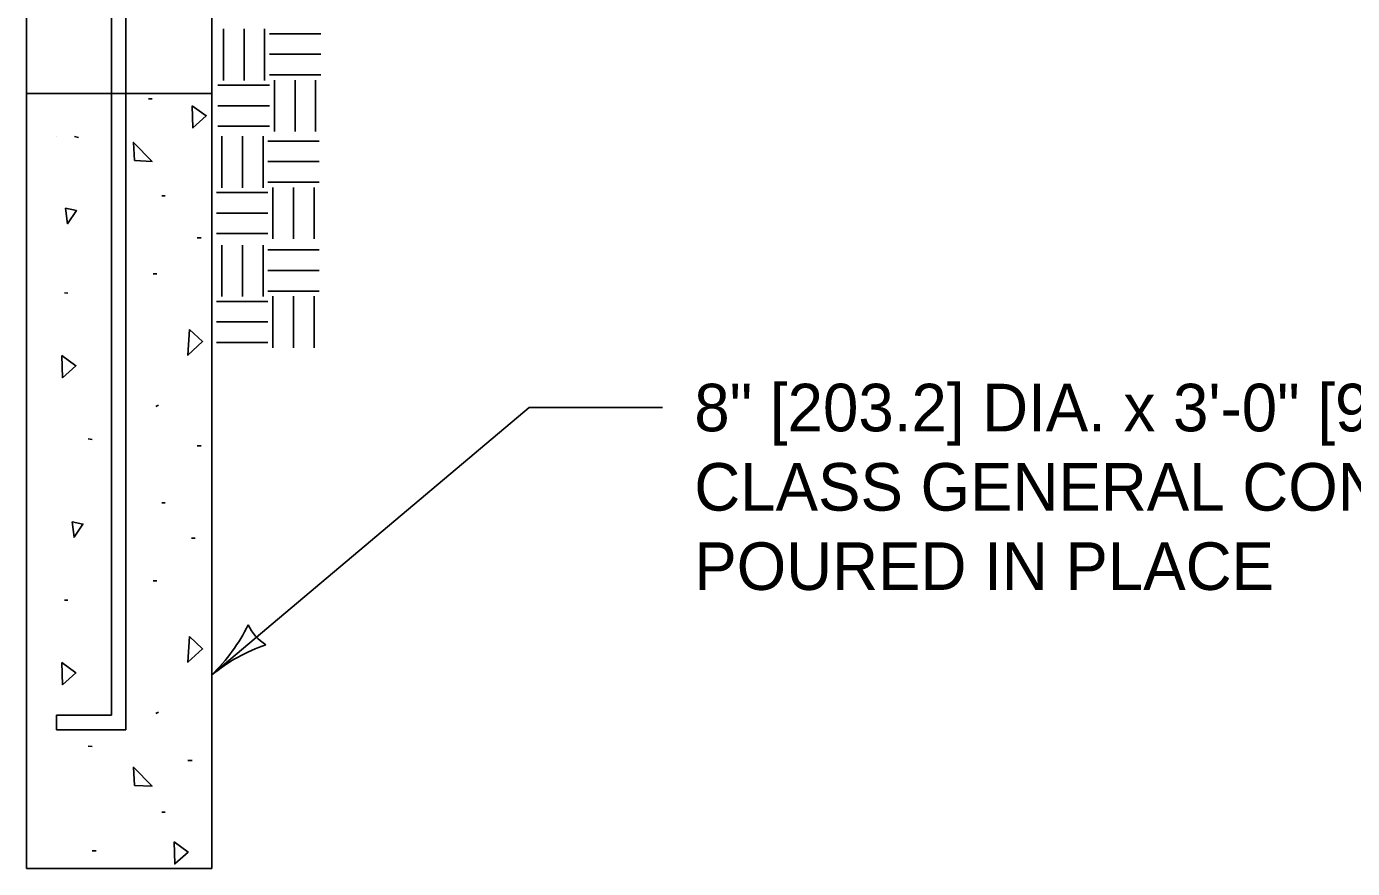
# Model space of a CAD drawing. Extents: x 49991.4 to 50021, y 49987.6 to 50011.4.
# Drawn here: x 50009.738 to 50011.41, y 49995.265 to 49996.327 of the extents above; entities that cross this region are included whole.
import ezdxf

# ---------------------------------------------------------------- set-up
doc = ezdxf.new("R2010")
doc.units = 0
for name, color, linetype in [('Level 1', 7, 'Continuous'), ('Level 2', 7, 'Continuous'), ('Level 3', 7, 'Continuous'), ('Level 4', 7, 'Continuous')]:
    doc.layers.add(name, color=color, linetype=linetype)

msp = doc.modelspace()

# ---------------------------------------------------------------- linework, layer by layer
at = {"layer": 'Level 1'}
for p, q in [((50009.8451, 49996.5973), (50009.8451, 49995.4586)), ((50009.8633, 49996.5973), (50009.8633, 49995.4401)), ((50009.9865, 49996.3237), (50009.9865, 49996.2589)), ((50010.0124, 49996.3237), (50010.0124, 49996.2589)), ((50010.0383, 49996.3237), (50010.0383, 49996.2589)), ((50010.0444, 49996.3177), (50010.1092, 49996.3177)), ((50010.0444, 49996.2918), (50010.1092, 49996.2918)), ((50010.0444, 49996.2658), (50010.1092, 49996.2658)), ((50009.9795, 49996.2528), (50010.0444, 49996.2528)), ((50010.0508, 49996.2593), (50010.0508, 49996.1945)), ((50010.0768, 49996.2593), (50010.0768, 49996.1945)), ((50010.1027, 49996.2593), (50010.1027, 49996.1945)), ((50009.7381, 49996.2425), (50009.9719, 49996.2425)), ((50009.7381, 49996.2425), (50009.7381, 49995.2651)), ((50009.892, 49996.2357), (50009.8964, 49996.2357)), ((50009.9719, 49995.2651), (50009.9719, 49996.2425)), ((50009.9795, 49996.2269), (50010.0444, 49996.2269)), ((50009.9795, 49996.2009), (50010.0444, 49996.2009)), ((50009.7764, 49996.1882), (50009.7764, 49996.1882)), ((50009.7987, 49996.1882), (50009.8037, 49996.187)), ((50009.9845, 49996.1883), (50009.9845, 49996.1235)), ((50010.0104, 49996.1883), (50010.0104, 49996.1235)), ((50010.0364, 49996.1883), (50010.0364, 49996.1235)), ((50010.0424, 49996.1823), (50010.1073, 49996.1823)), ((50010.0424, 49996.1564), (50010.1073, 49996.1564)), ((50009.9775, 49996.1175), (50010.0424, 49996.1175)), ((50010.0424, 49996.1304), (50010.1073, 49996.1304)), ((50010.0488, 49996.1239), (50010.0488, 49996.0591)), ((50010.0748, 49996.1239), (50010.0748, 49996.0591)), ((50010.1007, 49996.1239), (50010.1007, 49996.0591)), ((50009.9087, 49996.1134), (50009.913, 49996.1134)), ((50009.9775, 49996.0915), (50010.0424, 49996.0915)), ((50009.9775, 49996.0656), (50010.0424, 49996.0656)), ((50009.9533, 49996.0603), (50009.9582, 49996.0603)), ((50009.9845, 49996.051), (50009.9845, 49995.9862)), ((50010.0104, 49996.051), (50010.0104, 49995.9862)), ((50010.0364, 49996.051), (50010.0364, 49995.9862)), ((50010.0424, 49996.045), (50010.1073, 49996.045)), ((50009.8977, 49996.0149), (50009.9026, 49996.0149)), ((50010.0424, 49996.0191), (50010.1073, 49996.0191)), ((50009.7862, 49995.9909), (50009.7901, 49995.9904)), ((50010.0424, 49995.9931), (50010.1073, 49995.9931)), ((50010.0488, 49995.9866), (50010.0488, 49995.9218)), ((50010.0748, 49995.9866), (50010.0748, 49995.9218)), ((50010.1007, 49995.9866), (50010.1007, 49995.9218)), ((50009.9775, 49995.9801), (50010.0424, 49995.9801)), ((50009.9775, 49995.9542), (50010.0424, 49995.9542)), ((50009.9775, 49995.9283), (50010.0424, 49995.9283)), ((50009.9012, 49995.8477), (50009.9047, 49995.8491)), ((50009.8157, 49995.807), (50009.8209, 49995.806)), ((50009.9533, 49995.7979), (50009.9582, 49995.7979)), ((50009.9087, 49995.726), (50009.913, 49995.726)), ((50009.946, 49995.6814), (50009.9508, 49995.6814)), ((50009.8977, 49995.6277), (50009.9026, 49995.6277)), ((50009.7862, 49995.6034), (50009.7901, 49995.6034)), ((50009.8451, 49995.4586), (50009.7758, 49995.4586)), ((50009.7758, 49995.4586), (50009.7758, 49995.4401)), ((50009.9012, 49995.4605), (50009.9047, 49995.4621)), ((50009.8633, 49995.4401), (50009.7758, 49995.4401)), ((50009.8157, 49995.4195), (50009.8209, 49995.4189)), ((50009.9417, 49995.4011), (50009.9469, 49995.4011)), ((50009.9087, 49995.3361), (50009.913, 49995.3361)), ((50009.8211, 49995.2875), (50009.8259, 49995.2875)), ((50009.7381, 49995.2651), (50009.9719, 49995.2651))]:
    msp.add_line(p, q, dxfattribs=at)
for points in [[(50009.9471, 49996.2269), (50009.9647, 49996.2142), (50009.9479, 49996.1989)], [(50009.8744, 49996.1579), (50009.8964, 49996.1567), (50009.8729, 49996.1807)], [(50009.7873, 49996.0976), (50009.7898, 49996.078), (50009.801, 49996.0947)], [(50009.9437, 49995.9448), (50009.9601, 49995.9296), (50009.9416, 49995.9123)], [(50009.7827, 49995.9118), (50009.8003, 49995.8991), (50009.7835, 49995.8838)], [(50009.7956, 49995.7022), (50009.7981, 49995.6827), (50009.8093, 49995.6993)], [(50009.9437, 49995.5577), (50009.9601, 49995.542), (50009.9416, 49995.5252)], [(50009.7827, 49995.5248), (50009.8003, 49995.5117), (50009.7835, 49995.4968)], [(50009.8744, 49995.3699), (50009.8964, 49995.3689), (50009.8729, 49995.3928)], [(50009.9242, 49995.2988), (50009.9418, 49995.2857), (50009.925, 49995.2708)]]:
    msp.add_lwpolyline(points, close=True, dxfattribs=at)
at = {"layer": 'Level 3'}
for p, q in [((50010.372, 49995.8463), (50009.9719, 49995.5094)), ((50010.5403, 49995.8463), (50010.372, 49995.8463))]:
    msp.add_line(p, q, dxfattribs=at)
for centre, radius, start, end in [((50009.8092, 49995.6762), 0.233, 314.275, 333.5248), ((50010.068, 49995.5943), 0.0548, 203.5865, 239.3088), ((50010.1121, 49995.3368), 0.2223, 108.9037, 129.0872)]:
    msp.add_arc(centre, radius, start, end, dxfattribs=at)
at = {"layer": 'Level 4'}
for p, q in [((50009.7381, 49996.5919), (50009.7381, 49996.2425)), ((50009.9719, 49996.2425), (50009.9719, 49996.5919))]:
    msp.add_line(p, q, dxfattribs=at)

# ---------------------------------------------------------------- texts
at = {"layer": 'Level 2'}
for s, p in [('8" [203.2] DIA. x 3\'-0" [914.4] ', (50010.5803, 49995.8163)), ('CLASS GENERAL CONCRETE ANCHOR', (50010.5803, 49995.7163)), ('POURED IN PLACE', (50010.5803, 49995.6163))]:
    msp.add_text(s, height=0.06, dxfattribs=at).set_placement(p)

doc.saveas('drawing.dxf')
